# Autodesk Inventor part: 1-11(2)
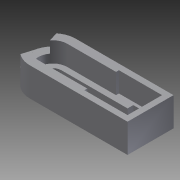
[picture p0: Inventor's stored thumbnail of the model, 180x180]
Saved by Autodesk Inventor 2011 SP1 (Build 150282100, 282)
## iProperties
Created: 2014-02
Part Number: 1-11(2)
Document SubType Name: Modeling
Designer: Administrator
Density: 1 g/cm^3
Author: Administrator
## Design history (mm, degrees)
sketch "草图1"
  geometry: L1 (-17, 8)-(17, 8); L2 (17, 8)-(17, -8); L3 (17, -8)-(-17, -8); A1 r 8 centre (-17, 0) between (-17, 8) and (-17, -8); 3 further points
  constraints: 6 end point, 2 midpoint, 2 point on circle, 1 centre point, 1 horizontal, 1 horizontal alignment, 1 parallel, 1 perpendicular, 1 vertical alignment
extrude "拉伸1" new body sketch "草图1" distance "d0" = 10; taper "d1" = 0 deg
sketch "草图2"
  geometry: L1 (0, -6)-(15, -6); L2 (15, -6)-(15, 6); L3 (15, 6)-(0, 6); L4 (0, -6)-(0, -5); L5 (0, 6)-(0, 5); L6 (0, -5)-(-17, -5); L7 (0, 5)-(-17, 5); A1 r 5 centre (-17, 0) between (-17, 5) and (-17, -5); 1 further point
  constraints: 14 end point, 2 perpendicular, 2 point on circle, 2 tangent, 1 centre point, 1 collinear
  dimensions: "d3" = 10 diameter of A1
extrude "拉伸2" cut sketch "草图2" distance "d4" = 7; taper "d5" = 0 deg
sketch "草图3"
  geometry: L1 (15, 6)-(0, 6) reference; L2 (0, -6)-(15, -6) reference; L3 (-17, -3)-(6, -3); L4 (-17, 3)-(6, 3); L5 (6, 3)-(6, 5); L6 (6, -3)-(6, -5); L7 (6, -5)-(12, -5); L8 (12, -5)-(12, 5); L9 (12, 5)-(6, 5); A1 r 5 centre (-17, 0) between (-17, 5) and (-17, -5) reference; A2 r 3 centre (-17, 0) between (-17, 3) and (-17, -3); 1 further point
  constraints: 14 end point, 5 parallel, 2 perpendicular, 2 point on circle, 2 tangent, 1 centre point, 1 coincident, 1 collinear
  dimensions: "d6" = 6 diameter of A2
extrude "拉伸3" cut sketch "草图3" distance "d8" = 7; taper "d9" = 0 deg
sketch "草图4"
  geometry: L1 (-17, -8)-(17, -8) reference; L2 (19.236, -2)-(26, -2); L3 (26, -2)-(26, 2); L4 (26, 2)-(19.236, 2); L5 (19.236, -2)-(19.236, 2); A1 r 3 centre (17, 0) between (17, -3) and (17, 3) reference; 1 further point
  constraints: 8 end point, 2 parallel, 2 perpendicular, 2 point on circle
extrude "拉伸4" cut sketch "草图4" distance "d10" = 1; taper "d11" = 0 deg
sketch "草图5"
  geometry: L1 (-24.746, 2)-(-19.236, 2) reference; L2 (-19.236, -2)-(-24.746, -2) reference; L3 (-21, 3)-(-21.991, 6.252); L4 (-21.991, -6.252)-(-21, -3); A1 r 5 centre (-17, 0) between (-17, 5) and (-17, -5) reference; A2 r 8 centre (-17, 0) between (-17, 8) and (-17, -8) reference; 1 further point
  constraints: 4 end point, 4 point on circle
extrude "拉伸5" cut sketch "草图5" distance "d12" = 4; taper "d13" = 0 deg
node "实体1"
